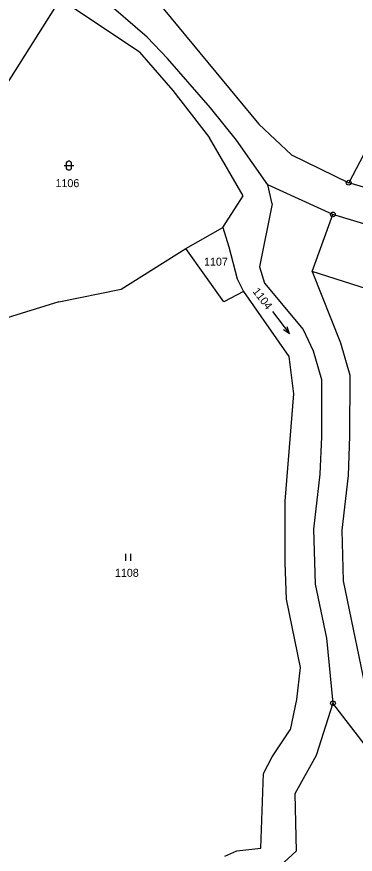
# Model space of a CAD drawing. Extents: x -796130 to -793145, y -1109506 to -1106267.
# Drawn here: x -794391.3 to -794319.4, y -1107830.1 to -1107652.3 of the extents above; entities that cross this region are included whole.
import ezdxf

# ---------------------------------------------------------------- set-up
doc = ezdxf.new("R2010")
doc.units = 0
for name, color, linetype in [('Vrstva 1', 7, 'Continuous'), ('Vrstva 14', 7, 'Continuous'), ('Vrstva 23', 7, 'Continuous'), ('Vrstva 28', 7, 'Continuous')]:
    doc.layers.add(name, color=color, linetype=linetype)

msp = doc.modelspace()

# ---------------------------------------------------------------- linework, layer by layer
at = {"layer": 'Vrstva 1'}
for p, q in [((-794286.09, -1107621.32), (-794320.82, -1107687.54)), ((-794363.6, -1107656.68), (-794377.15, -1107644.78)), ((-794382.04, -1107648.53), (-794402.09, -1107680.28)), ((-794365.2, -1107659.81), (-794382.04, -1107648.53)), ((-794361.53, -1107648.94), (-794339.86, -1107675.09)), ((-794359.28, -1107661.17), (-794363.6, -1107656.68)), ((-794365.2, -1107659.81), (-794358.17, -1107667.97)), ((-794350.17, -1107671.65), (-794359.28, -1107661.17)), ((-794358.17, -1107667.97), (-794350.33, -1107678.03)), ((-794344.66, -1107678.54), (-794350.17, -1107671.65)), ((-794339.86, -1107675.09), (-794332.97, -1107681.61)), ((-794343.23, -1107690.31), (-794350.33, -1107678.03)), ((-794337.95, -1107688.02), (-794344.66, -1107678.54)), ((-794332.97, -1107681.61), (-794320.82, -1107687.54)), ((-794226.57, -1107716.47), (-794320.82, -1107687.54)), ((-794324.16, -1107694.29), (-794337.95, -1107688.02)), ((-794337.08, -1107692.03), (-794337.95, -1107688.02)), ((-794347.5, -1107697.06), (-794343.23, -1107690.31)), ((-794337.08, -1107692.03), (-794339.78, -1107705.37)), ((-794328.57, -1107706.41), (-794324.16, -1107694.29)), ((-794296.73, -1107702.53), (-794324.16, -1107694.29)), ((-794355.37, -1107701.53), (-794347.5, -1107697.06)), ((-794347.5, -1107697.06), (-794346.28, -1107701.19)), ((-794369.12, -1107710.16), (-794355.37, -1107701.53)), ((-794347.34, -1107712.82), (-794355.37, -1107701.53)), ((-794346.28, -1107701.19), (-794344.46, -1107707.93)), ((-794339.78, -1107705.37), (-794338.65, -1107708.87)), ((-794328.57, -1107706.41), (-794322.58, -1107721.56)), ((-794279.53, -1107721.92), (-794328.57, -1107706.41)), ((-794344.46, -1107707.93), (-794343.17, -1107710.65)), ((-794338.65, -1107708.87), (-794330.48, -1107718.69)), ((-794382.35, -1107712.86), (-794369.12, -1107710.16)), ((-794343.17, -1107710.65), (-794347.34, -1107712.82)), ((-794343.17, -1107710.65), (-794333.5, -1107724.47)), ((-794382.35, -1107712.86), (-794398.91, -1107717.92)), ((-794330.48, -1107718.69), (-794328.34, -1107723.23)), ((-794322.58, -1107721.56), (-794320.6, -1107728.4)), ((-794333.5, -1107724.47), (-794332.5, -1107732.39)), ((-794328.34, -1107723.23), (-794326.58, -1107729.32)), ((-794320.6, -1107728.4), (-794320.61, -1107741.38)), ((-794326.58, -1107729.32), (-794326.61, -1107741.48)), ((-794332.5, -1107732.39), (-794334.38, -1107755.13)), ((-794326.61, -1107741.48), (-794326.93, -1107749.43)), ((-794320.61, -1107741.38), (-794320.93, -1107749.67)), ((-794326.93, -1107749.43), (-794328.25, -1107761.06)), ((-794320.93, -1107749.67), (-794322.24, -1107761.32)), ((-794334.38, -1107755.13), (-794334.38, -1107768.25)), ((-794328.25, -1107761.06), (-794327.94, -1107772.75)), ((-794322.24, -1107761.32), (-794321.96, -1107772.05)), ((-794334.38, -1107768.25), (-794334.11, -1107775.94)), ((-794327.94, -1107772.75), (-794325.53, -1107784.22)), ((-794321.96, -1107772.05), (-794316.55, -1107798.35)), ((-794334.11, -1107775.94), (-794331.09, -1107790.44)), ((-794325.53, -1107784.22), (-794324.15, -1107798.06)), ((-794331.09, -1107790.44), (-794331.89, -1107797.23)), ((-794331.89, -1107797.23), (-794333.25, -1107803.72)), ((-794324.15, -1107798.06), (-794327.7, -1107809.17)), ((-794317.34, -1107806.92), (-794324.15, -1107798.06)), ((-794337.04, -1107809.42), (-794333.25, -1107803.72)), ((-794338.87, -1107812.94), (-794337.04, -1107809.42)), ((-794327.7, -1107809.17), (-794332.26, -1107817.3)), ((-794339.46, -1107828.79), (-794338.87, -1107812.94)), ((-794332.26, -1107817.3), (-794331.93, -1107829.42)), ((-794347.08, -1107830.5), (-794344.59, -1107829.39)), ((-794344.59, -1107829.39), (-794339.46, -1107828.79)), ((-794331.93, -1107829.42), (-794336.96, -1107834.02))]:
    msp.add_line(p, q, dxfattribs=at)
at = {"layer": 'Vrstva 23'}
for p, q in [((-794381.19, -1107683.91), (-794379.19, -1107683.91)), ((-794380.69, -1107683.31), (-794380.59, -1107683.11)), ((-794380.69, -1107684.51), (-794380.69, -1107683.31)), ((-794380.59, -1107683.11), (-794380.49, -1107683.01)), ((-794380.49, -1107683.01), (-794380.29, -1107682.91)), ((-794380.29, -1107682.91), (-794380.09, -1107682.91)), ((-794380.09, -1107682.91), (-794379.89, -1107683.01)), ((-794379.89, -1107683.01), (-794379.79, -1107683.11)), ((-794379.79, -1107683.11), (-794379.69, -1107683.31)), ((-794379.69, -1107683.31), (-794379.69, -1107684.51)), ((-794380.59, -1107684.71), (-794380.69, -1107684.51)), ((-794380.49, -1107684.81), (-794380.59, -1107684.71)), ((-794380.29, -1107684.91), (-794380.49, -1107684.81)), ((-794380.09, -1107684.91), (-794380.29, -1107684.91)), ((-794379.89, -1107684.81), (-794380.09, -1107684.91)), ((-794379.79, -1107684.71), (-794379.89, -1107684.81)), ((-794379.69, -1107684.51), (-794379.79, -1107684.71)), ((-794336.979, -1107714.857), (-794333.36, -1107719.642)), ((-794333.36, -1107719.642), (-794334.663, -1107718.747)), ((-794333.36, -1107719.642), (-794333.866, -1107718.144)), ((-794368.15, -1107767.83), (-794368.15, -1107766.33)), ((-794367.15, -1107766.33), (-794367.15, -1107767.83))]:
    msp.add_line(p, q, dxfattribs=at)
at = {"layer": 'Vrstva 28'}
for centre, radius in [((-794320.82, -1107687.54), 0.5), ((-794320.82, -1107687.54), 0.01), ((-794324.16, -1107694.29), 0.5), ((-794324.16, -1107694.29), 0.01), ((-794324.15, -1107798.06), 0.5), ((-794324.15, -1107798.06), 0.01)]:
    msp.add_circle(centre, radius, dxfattribs=at)

# ---------------------------------------------------------------- texts
at = {"layer": 'Vrstva 14'}
for s, p in [('1106', (-794383.052, -1107688.49)), ('1107', (-794351.519, -1107705.16)), ('1108', (-794370.432, -1107771.21))]:
    msp.add_text(s, height=1.7, dxfattribs=at).set_placement(p)
msp.add_text('1104', height=1.7, rotation=307.8, dxfattribs=at).set_placement((-794341.314, -1107710.65))

doc.saveas('drawing.dxf')
